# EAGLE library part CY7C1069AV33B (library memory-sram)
2M x 8 Static RAM Source: CYPRESS cy7c1069av33_8.pdf
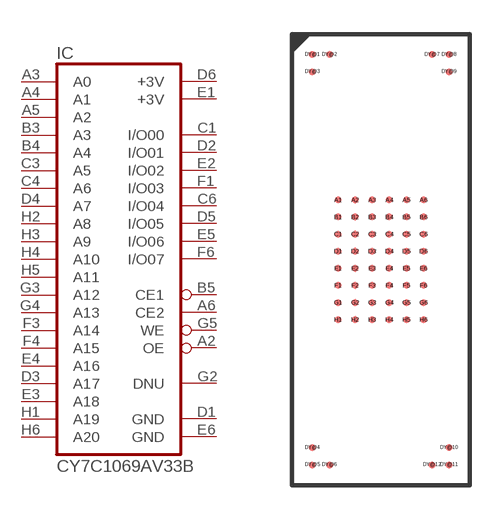
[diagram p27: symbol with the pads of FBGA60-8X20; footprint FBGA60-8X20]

Designator prefix IC

## CY7C1069AV33B  [FBGA60-8X20]
A2  OE  in
A3  A0  in
A4  A1  in
A5  A2  in
A6  CE2  in
B3  A3  in
B4  A4  in
B5  CE1  in
C1  I/O00
C3  A5  in
C4  A6  in
C6  I/O04
D1  GND  pwr
D2  I/O01
D3  A17  in
D4  A7  in
D5  I/O05
D6  +3V  pwr
E1  +3V  pwr
E2  I/O02
E3  A18  in
E4  A16  in
E5  I/O06
E6  GND  pwr
F1  I/O03
F3  A14  in
F4  A15  in
F6  I/O07
G2  DNU  pas
G3  A12  in
G4  A13  in
G5  WE  in
H1  A19  in
H2  A8  in
H3  A9  in
H4  A10  in
H5  A11  in
H6  A20  in

## Footprint FBGA60-8X20 (pad centres in mm)
60-ball FBGA (8 mm x 20 mm x 1.2 mm) (51-85162) Source: CYPRESS cy7c1069av33_8.pdf
smd 0.3 x 0.3: A1 -1.875,2.625; A2 -1.125,2.625; A3 -0.375,2.625; A4 0.375,2.625; A5 1.125,2.625; A6 1.875,2.625; B1 -1.875,1.875; B2 -1.125,1.875; B3 -0.375,1.875; B4 0.375,1.875; B5 1.125,1.875; B6 1.875,1.875; C1 -1.875,1.125; C2 -1.125,1.125; C3 -0.375,1.125; C4 0.375,1.125; C5 1.125,1.125; C6 1.875,1.125; D1 -1.875,0.375; D2 -1.125,0.375; D3 -0.375,0.375; D4 0.375,0.375; D5 1.125,0.375; D6 1.875,0.375; DY@1 -3,9; DY@2 -2.25,9; DY@3 -3,8.25; DY@4 -3,-8.25; DY@5 -3,-9; DY@6 -2.25,-9; DY@7 2.25,9; DY@8 3,9; DY@9 3,8.25; DY@10 3,-8.25; DY@11 3,-9; DY@12 2.25,-9; E1 -1.875,-0.375; E2 -1.125,-0.375; E3 -0.375,-0.375; E4 0.375,-0.375; E5 1.125,-0.375; E6 1.875,-0.375; F1 -1.875,-1.125; F2 -1.125,-1.125; F3 -0.375,-1.125; F4 0.375,-1.125; F5 1.125,-1.125; F6 1.875,-1.125; G1 -1.875,-1.875; G2 -1.125,-1.875; G3 -0.375,-1.875; G4 0.375,-1.875; G5 1.125,-1.875; G6 1.875,-1.875; H1 -1.875,-2.625; H2 -1.125,-2.625; H3 -0.375,-2.625; H4 0.375,-2.625; H5 1.125,-2.625; H6 1.875,-2.625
